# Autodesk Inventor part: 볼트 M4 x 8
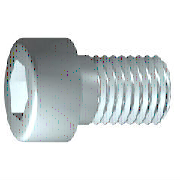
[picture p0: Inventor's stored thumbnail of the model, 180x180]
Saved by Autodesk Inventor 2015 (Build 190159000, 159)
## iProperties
IsCustomPart: 1
Created: 2012-02
Part Number: 볼트 M4 x 8
Material: 스테인리스강
Description: 6각 소켓 머리 캡 나사
Document SubType Name: Modeling
Standard: ISO 4762
Designer: mduedu
Standard Revision: Fourth edition 2004-03-01
Standards Organization: ISO
Language: ko-KR
Size Designation: M4 x 8
Categories: <MemberInstance><Categories><Category DisplayName="조임쇠" InternalName="e4da775c-781d-43d5-af7c-5136215cf5a6" Mnemonic="FSTN"><Category DisplayName="볼트" InternalN
Density: 7.75 g/cm^3
Appearance: 반광택
Author: mduedu
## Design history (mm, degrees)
sketch "스케치1"
  geometry: L1 (-1, 0)-(8, 0); L2 (8, 0)-(8, 2); L3 (8, 2)-(1.75, 2); L4 (1.75, 2)-(1.32, 2); L5 (1.32, 2)-(0, 2); L6 (0, 2)-(0, 3.5); L7 (0, 3.5)-(-4, 3.5); L8 (-4, 3.5)-(-4, 1.732); L9 (-4, 1.732)-(-2, 1.732); L10 (-2, 1.732)-(-1, 0); L11 (-6.4, 0)-(10.4, 0) reference; L12 (0, -0.7)-(0, 4.2) reference; L13 (1.75, 2)-(0, 2)
  constraints: 22 end point, 6 parallel, 2 collinear, 2 perpendicular, 1 horizontal, 1 point on line
  dimensions: "d1" = 6.25 distance from line of L3.end L2 (= GEL); "d2" = 0.42952 distance of L4.end L3.end (computed from GAL); "d3" = 4 distance between parallel lines of L8 L6 (= KOH); "d4" = 2 distance of L8.end L9.end (= INTI); "d5" = 60 deg angle of L10 L1; "d6" = 4 diameter of L3 L1 (= GD); "d7" = 4 diameter of L5 L1 (= BDM); "d8" = 3.4641 diameter of L9 L1 (= 1.1547 x SW); "d9" = 7 diameter of L7 L1 (= KOD); "d26" = 8 distance between parallel lines of L12 L2 (= NLG)
revolve "본체" sketch "스케치1" stored, may be unused: angle "d10" = 90 deg
sketch "스케치2"
  geometry: L1 (0, -4.9)-(0, 4.9) reference; L2 (-4.9, 0)-(4.9, 0) reference; L3 (1.732, 0)-(0.866, -1.5); L4 (0.866, -1.5)-(-0.866, -1.5); L5 (-0.866, -1.5)-(-1.732, 0); L6 (-1.732, 0)-(-0.866, 1.5); L7 (-0.866, 1.5)-(0.866, 1.5); L8 (0.866, 1.5)-(1.732, 0); 2 further points
  constraints: 12 end point, 1 coincident, 1 horizontal alignment, 1 point on line, 12 other
extrude "슬롯" join sketch "스케치2" stored distance "d11" = 10; taper "d12" = 0 deg
workplane "Work Plane1"
fillet "Fillet2" dims "d30" = 0.1 (= R)
body "Solid1"
fillet "모깎기1" dims "d17" = 0.4 (= RR)
feature "스레드" dims "d13" = 6.25 (= GEL), "d14" = 0
chamfer "모따기1" distance "d15" = 0.42941 (= -0.5 x SPD + 0.5 x GD); stored, may be unused: second distance "d16" = 0.42941 (= GUL), angle "d27" = 45 deg
other parameters: "GD" = 4 [user parameter; used in 2 equation terms], "NLG" = 8 [user parameter; used in 1 equation term], "GEL" = 6.25 [user parameter; used in 2 equation terms], "KOD" = 7 [user parameter; used in 1 equation term], "KOH" = 4 [user parameter; used in 1 equation term], "INTI" = 2 [user parameter; used in 1 equation term], "GAL" = 0.42941 (= 0.61345 x PTC) [user parameter; used in 1 equation term], "GUL" = 0.42941 (= 0.61345 x PTC) [user parameter; used in 1 equation term], "BDM" = 4 (= NND) [user parameter; used in 1 equation term], "SW" = 3 [user parameter; used in 2 equation terms], "RR" = 0.4 [user parameter; used in 1 equation term], "SPD" = 3.14117 (= NND - 1.2269 x PTC) [user parameter; used in 1 equation term], "d19" = 0, "d28" = 0, "d29" = 0, "R" = 0.1 [user parameter; used in 1 equation term], "TOA" = 30 deg [user parameter], "GD1" = 3.14117 (= THREADDIA - 1.2269 x PTC) [user parameter], "THREADDIA" = 4 [user parameter; used in 1 equation term], "FAWI" = 45 deg [user parameter], "TPU" = 14.28571 (computed from PTC) [user parameter], "PTC" = 0.7 [user parameter; used in 5 equation terms], "NND" = 4 [user parameter; used in 2 equation terms], "E0" = 3.465 (= 1.155 x SW) [user parameter]
